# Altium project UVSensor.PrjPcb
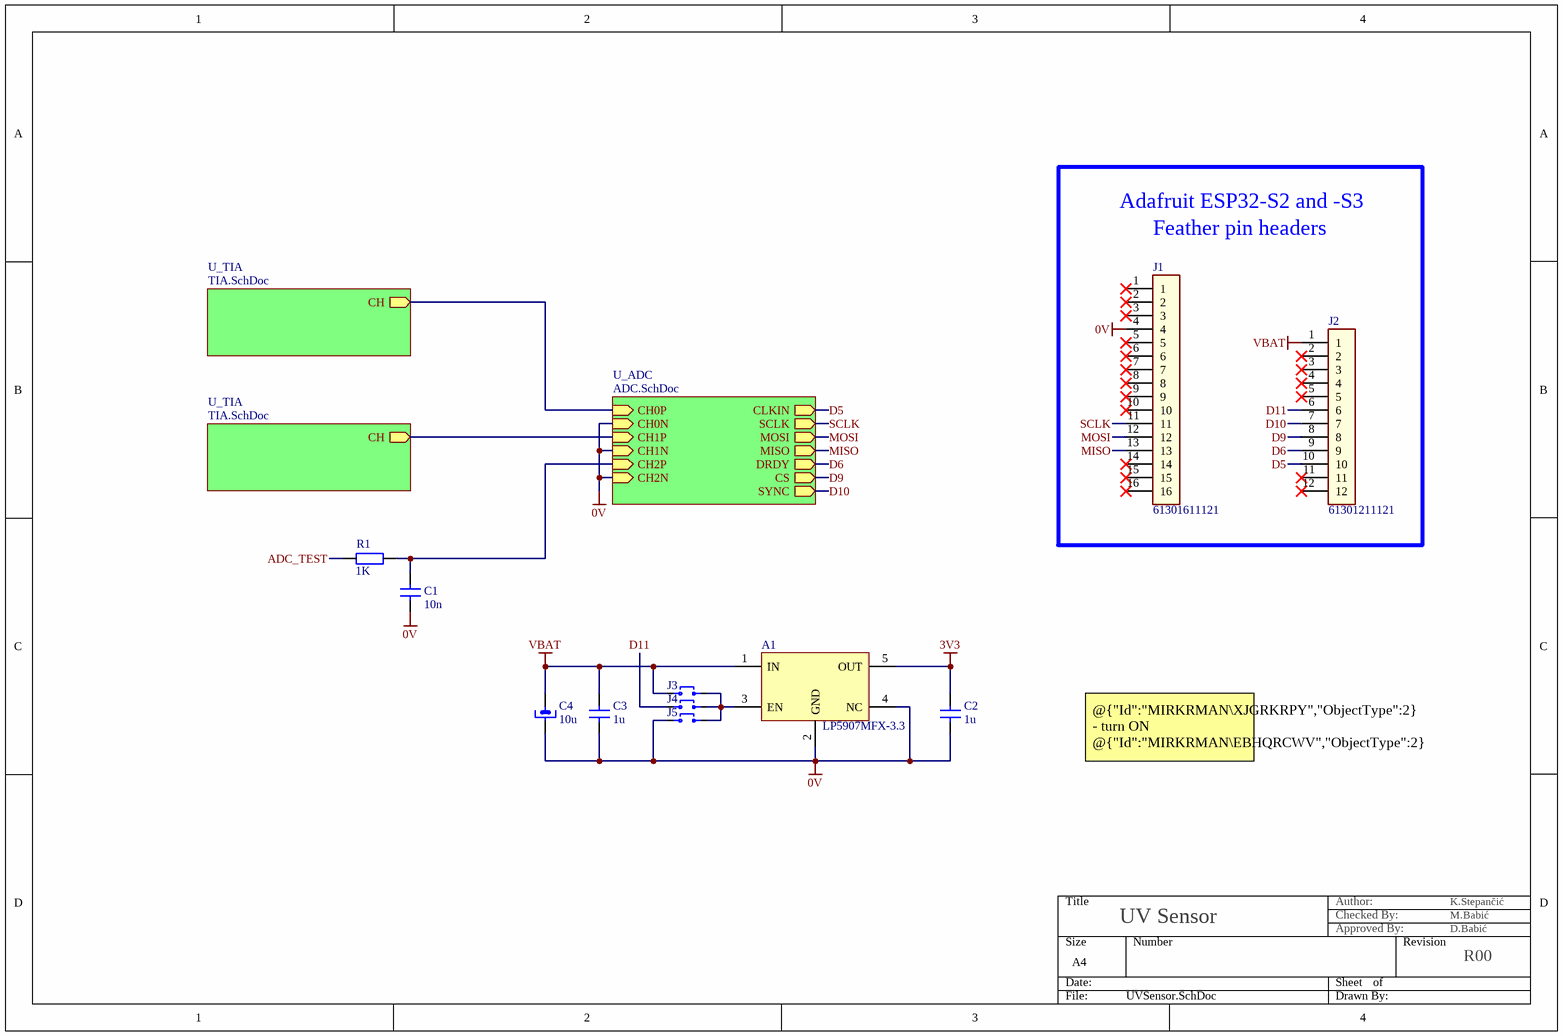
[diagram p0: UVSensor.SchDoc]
K_ApprovedBy: D.Babić; K_AssyNum: A00Z0NE; K_AssyRevision: 00; K_AssySheet: 1; K_AssySheetL1: 1; K_AssySheetL2: 2; K_AssySheetL3: 3; K_AssySheetL4: 4; K_AssySheets: 4; K_Fiet: fiet 40422a/2; K_FIET: fiet 40422a/2; K_LMOSheet: 1; K_LMOSheets: 1; K_PcbDate: 29.5.2025.; K_PcbNum: PB00TIA; K_PcbRevision: 00; K_SchAuthor: K.Stepančić; K_SchCheckedBy: M.Babić; K_SchDate: 29.5.2025.; K_SchNum: S00Z0NE; K_SchRevision: 00; K_Title: UV SENSOR; K_Title1: FerSat; VariantDescription: --
3 sheets, 63 parts. Net scope: hierarchical (ports join the sheet entries above them; power ports are global).
Board file: PB00TIA.PcbDoc
Sheets:
  UVSensor.SchDoc
    U_ADC = ADC.SchDoc
    U_TIA = TIA.SchDoc
    U_TIA = TIA.SchDoc

## Sheet UVSensor.SchDoc: UV Sensor
size A4; ApprovedBy: D.Babić; CheckedBy: M.Babić; Author: K.Stepančić; DrawnBy: K.Stepančić; Engineer: K.Stepančić; DocumentNumber: S00Z0NE; Revision: R00; SheetNumber: 1; SheetTotal: 3; SheetName1: Sensor Board UV; PageSetup: Record=PageOptions¦CenterHorizontal=True¦CenterVertical=True¦PrintScale=1.01¦XCorrection=1.00¦YCorrection=1.00¦PrintKind=0¦BorderSize=5000000¦LeftOffset=0¦BottomOffset=0¦Orientation=2¦PaperLength=1000¦PaperWidth=1000¦Scale=100¦PaperSource=7¦PrintQuality=600¦MediaType=1¦DitherType=10¦PaperKind=A3¦PrintScaleMode=1; SheetName2: SheetName2

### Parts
A1  value LP5907MFX-3.3  [SOT95P280X145-5M]  (hidden comment: LP5907MFX-3.3/NOPB)
C1  10n  [CAPC2012X14M]
C2  1u  [CAPC2012X14M]
C3  1u  [CAPC2012X14M]
C4  value 10u  [CAPMP7343X31M]  (hidden comment: TC_LESR_10u_35V_20%)
J1  61301611121  [HDRV16W79P0X254_1X16_4064X254X874P]
J2  61301211121  [HDRV12W79P0X254_1X12_3048X254X874P]
J3  61300211121  [HDRV2W110P0X254_1X2_508X254X854P]  (value not drawn)
J4  61300211121  [HDRV2W110P0X254_1X2_508X254X854P]  (value not drawn)
J5  61300211121  [HDRV2W110P0X254_1X2_508X254X854P]  (value not drawn)
R1  1K  [RESC2112X05M]

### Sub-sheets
U_ADC = ADC.SchDoc: CH0P (in), CH0N (in), CH1N (in), CH1P (in), CH2P (in), CH2N (in), MOSI (out), MISO (out), SCLK (out), DRDY (out), CS (out), SYNC (out), CLKIN (out)
U_TIA = TIA.SchDoc: CH (out)
U_TIA = TIA.SchDoc: CH (out)

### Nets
0V: A1.2(GND) A1.4(NC) C1.2 C2.2 C3.2 C4.2 J1.4 J5.2 ; sheet U_ADC/CH0N, sheet U_ADC/CH1N, sheet U_ADC/CH2N
3V3: A1.5(OUT) C2.1
VBAT: A1.1(IN) C3.1 C4.1 J2.1 J3.2
ADC_TEST: R1.1
D5: J2.10 ; sheet U_ADC/CLKIN
D6: J2.9 ; sheet U_ADC/DRDY
D9: J2.8 ; sheet U_ADC/CS
D10: J2.7 ; sheet U_ADC/SYNC
D11: J2.6 J4.2
MISO: J1.13 ; sheet U_ADC/MISO
MOSI: J1.12 ; sheet U_ADC/MOSI
SCLK: J1.11 ; sheet U_ADC/SCLK
NetA1_3: A1.3(EN) J3.1 J4.1 J5.1
NetC1_1: C1.1 R1.2 ; sheet U_ADC/CH2P
NetC12:1_1: sheet U_ADC/CH0P, sheet U_TIA/CH
NetC12:2_1: sheet U_ADC/CH1P, sheet U_TIA/CH

Not connected (* = marked no-connect by the designer): J1 1* 2* 3* 5* 6* 7* 8* 9* 10* 14* 15* 16*; J2 2* 3* 4* 5* 11* 12*

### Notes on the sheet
- Adafruit ESP32-S2 and -S3
- (near J1) Feather pin headers
- @{"Id":"MIRKRMAN\XJGRKRPY","ObjectType":2} - turn ON
  @{"Id":"MIRKRMAN\EBHQRCWV","ObjectType":2} - control with GPIO11
  @{"Id":"MIRKRMAN\NMVCMQXM","ObjectType":2} - turn OFF
- Author:
- Checked By:
- Approved By:

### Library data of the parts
A1 = CMP-1291-0A: LDO Voltage Regulators 250mA Ultra-Lo Noise LDO Reg; Manufacturer: Texas Instruments; Voltage: 2.2V to 5.5V
C1 = CAPC2012X14M: C0805H103K5GACTU, / Multilayer Ceramic Capacitors MLCC - SMD/SMT 50V 0.01uF C0G 0805 10%
C2 C3 = CAPC2012X14M: C0805C105K5RACTU, Multilayer Ceramic Capacitors MLCC - SMD/SMT 50V 1uF X7R 0805 10%
C4 = CMP-0312-0D: Capacitor, Tantalum, 10uF, 35V, 20%, Low ESR, 250mΩ, Kemet; ManufacturerPartNumber: T495D106M035ATE250; ValueNumeric: 10000000
J1 = 61301611121: Connector; Manufacturer_Name: Wurth Elektronik
J2 = 61301211121: Connector; Manufacturer_Name: Wurth Elektronik
J3-J5 = 61300211121: Connector; Manufacturer_Name: Wurth Elektronik
R1 = RESC2112X05M: CRCW08051K00JNEC, Thick Film Resistors D12/CRCW0805 200 1K0 5% ET6 e3

## Sheet ADC.SchDoc: ADC
size A4; ApprovedBy: D.Babić; CheckedBy: M.Babić; Author: K.Stepančić; Revision: R00; SheetNumber: 3; SheetTotal: 3
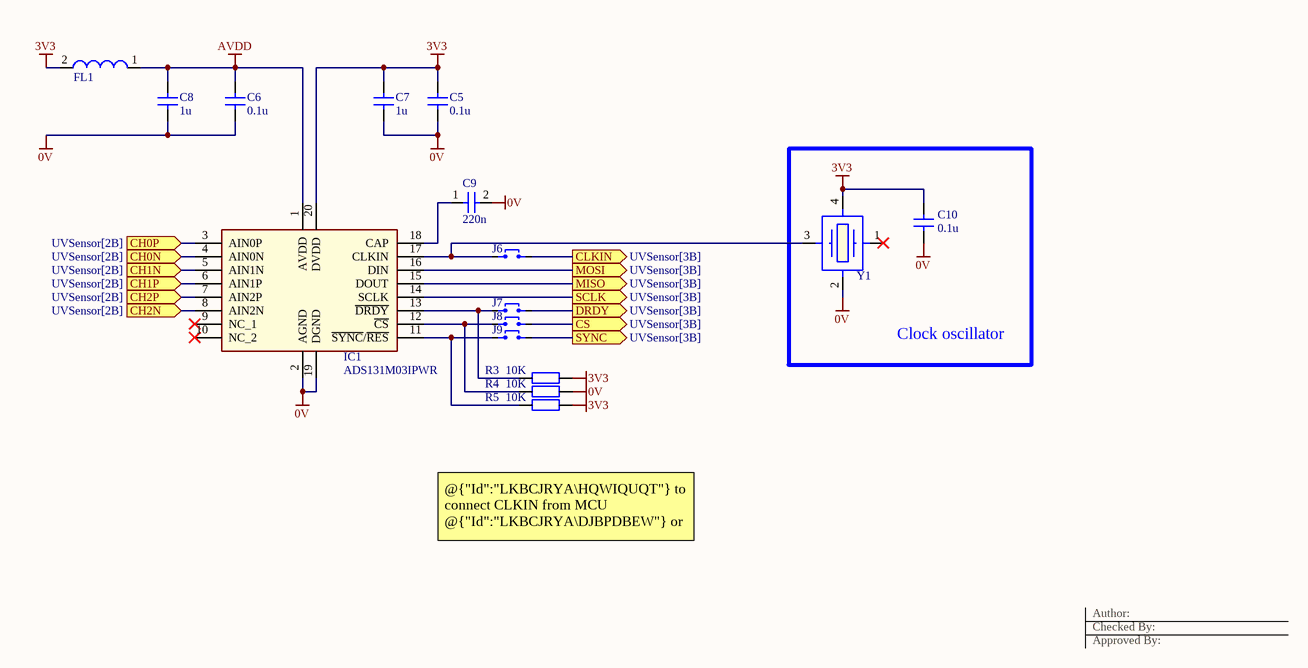
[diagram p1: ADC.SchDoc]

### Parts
C5  0.1u  [CAPC2012X14M]
C6  0.1u  [CAPC2012X14M]
C7  1u  [CAPC2012X14M]
C8  1u  [CAPC2012X14M]
C9  220n  [C_0603]
C10  0.1u  [CAPC2012X14M]
FL1  BLM21SP601BH1D  [BLM21AG102BH1J]  (value not drawn)
IC1  ADS131M03IPWR  [SOP65P640X120-20N]
J6  61300211121  [HDRV2W110P0X254_1X2_508X254X854P]  (value not drawn)
J7  61300211121  [HDRV2W110P0X254_1X2_508X254X854P]  (value not drawn)
J8  61300211121  [HDRV2W110P0X254_1X2_508X254X854P]  (value not drawn)
J9  61300211121  [HDRV2W110P0X254_1X2_508X254X854P]  (value not drawn)
R3  10K  [RESC2112X05M]
R4  10K  [RESC2112X05M]
R5  10K  [RESC2112X05M]
Y1  ECS-2520MVLC-020-BN-TR  [ECS2520MVLC020BNTR]  (value not drawn)

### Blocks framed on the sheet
Clock oscillator: C10 Y1

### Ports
CH0N (in, see UVSensor[2B]), CH0P (in, see UVSensor[2B]), CH1N (in, see UVSensor[2B]), CH1P (in, see UVSensor[2B]), CH2N (in, see UVSensor[2B]), CH2P (in, see UVSensor[2B]), CLKIN (out, see UVSensor[3B]), CS (out, see UVSensor[3B]), DRDY (out, see UVSensor[3B]), MISO (out, see UVSensor[3B]), MOSI (out, see UVSensor[3B]), SCLK (out, see UVSensor[3B]), SYNC (out, see UVSensor[3B])

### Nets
0V: C5.2 C6.2 C7.2 C8.2 C9.2 C10.2 IC1.2(AGND) IC1.4(AIN0N) IC1.5(AIN1N) IC1.8(AIN2N) IC1.19(DGND) R4.2 Y1.2(GND) ; port CH0N, port CH1N, port CH2N
3V3: C5.1 C7.1 C10.1 FL1.2 IC1.20(DVDD) R3.2 R5.2 Y1.4(VDD)
AVDD: C6.1 C8.1 FL1.1 IC1.1(AVDD)
D5: J6.2 ; port CLKIN
D6: J7.2 ; port DRDY
D9: J8.2 ; port CS
D10: J9.2 ; port SYNC
MISO: IC1.15(DOUT) ; port MISO
MOSI: IC1.16(DIN) ; port MOSI
SCLK: IC1.14(SCLK) ; port SCLK
NetC1_1: IC1.7(AIN2P) ; port CH2P
NetC9_1: C9.1 IC1.18(CAP)
NetC12:1_1: IC1.3(AIN0P) ; port CH0P
NetC12:2_1: IC1.6(AIN1P) ; port CH1P
NetIC1_11: IC1.11(~{SYNC}/~{RES}) J9.1 R5.1
NetIC1_12: IC1.12(~{CS}) J8.1 R4.1
NetIC1_13: IC1.13(~{DRDY}) J7.1 R3.1
NetIC1_17: IC1.17(CLKIN) J6.1 Y1.3(OUTPUT)

Not connected (* = marked no-connect by the designer): IC1 9(NC_1)* 10(NC_2)*; Y1 1(TRI-STATE)*

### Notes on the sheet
- @{"Id":"LKBCJRYA\HQWIQUQT"} to connect CLKIN from MCU
  @{"Id":"LKBCJRYA\DJBPDBEW"} or @{"Id":"LKBCJRYA\RAQNGLEC"} to select DRDY or SYNC
  @{"Id":"LKBCJRYA\YJMZBBWQ"} to enable CS
- Author:
- Checked By:
- Approved By:

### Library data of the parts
C5 C6 C10 = CAPC2012X14M: C0805C104K5RACTU, Multilayer Ceramic Capacitors MLCC - SMD/SMT 50V 0.1uF X7R 0805 10%
C7 C8 = CAPC2012X14M: as C2 on sheet UVSensor
C9 = CAP_0603: Capacitor 0603
FL1 = BLM21SP601BH1D: BLM18PG181SN1D; Manufacturer_Name: Murata Electronics
IC1 = ADS131M03IPWR: Integrated Circuit; Manufacturer_Name: Texas Instruments
J6-J9 = 61300211121: as J3 on sheet UVSensor
R3-R5 = RESC2112X05M: CRCW080510K0FKEA, Thick Film Resistors 1/8watt 10Kohms 1% 100ppm
Y1 = ECS-2520MVLC-020-BN-TR: ECS-2520MVLC-081.92-BN-TR, Standard Clock Oscillators MultiVolt ECS-2520MVLC,Active,XO (Standard),8.192MHz,Enable/Disable,CMOS,1.8V, 2.5V, 3.3V,+/-50ppm,-40 C 85 C,Surface Mount,4-SMD, No Lead,0.098" L x 0.079" W (2.50mm x 2.00mm),0.035" (0.90mm); Manufacturer_Name: ECS

## Sheet TIA.SchDoc: TIA LMP7721
size A4; ApprovedBy: D.Babić; CheckedBy: M.Babić; Author: K.Stepančić; Revision: R00; SheetNumber: 2; SheetTotal: 3
Used 2 times, as channels U_TIA, U_TIA. Parts and nets are listed once, with the designators drawn on the sheet.
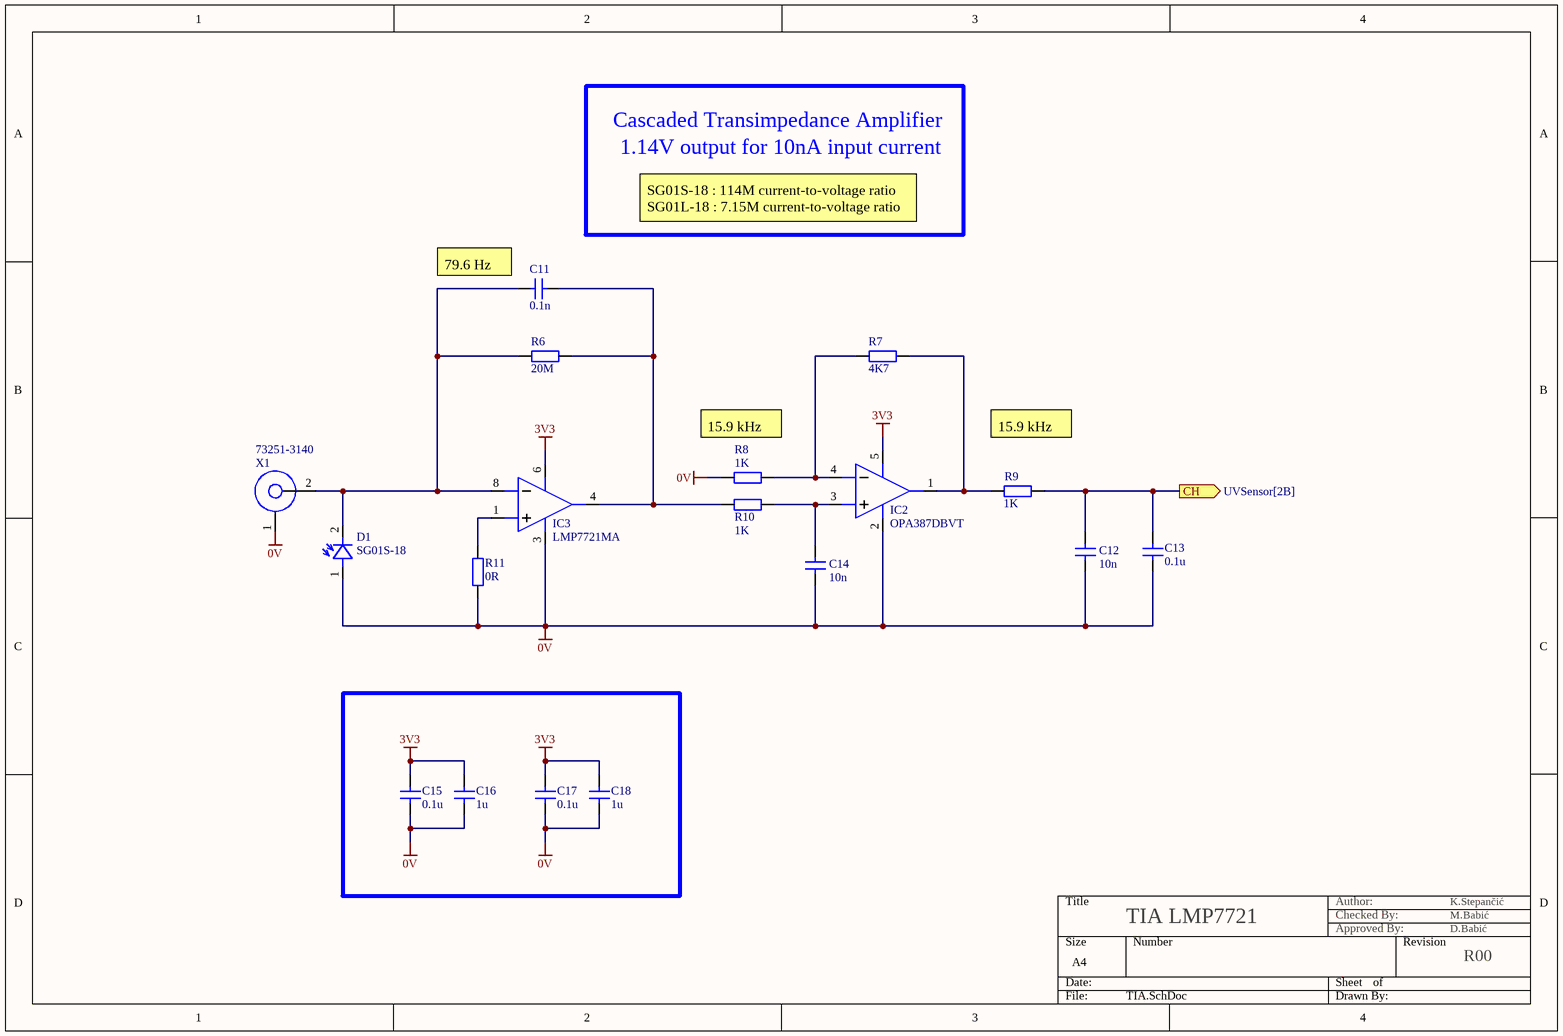
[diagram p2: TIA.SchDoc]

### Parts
C11  0.1n  [CAPC2012X14M]
C12  10n  [CAPC2012X14M]
C13  0.1u  [CAPC2012X14M]
C14  10n  [CAPC2012X14M]
C15  0.1u  [CAPC2012X14M]
C16  1u  [CAPC2012X14M]
C17  0.1u  [CAPC2012X14M]
C18  1u  [CAPC2012X14M]
D1  SG01S-18  [TO18]
IC2  OPA387DBVT  [SOT95P280X145-5N]
IC3  LMP7721MA  [SOIC127P600X175-8N]
R6  20M  [RESC3216X76N]
R7  value 4K7  [RESC2112X05M]  (hidden comment: RES_4K7_0805_1%)
R8  1K  [RESC2112X05M]
R9  1K  [RESC2112X05M]
R10  1K  [RESC2112X05M]
R11  0R  [RESC2112X05M]
X1  73251-3140  [73251-3140]

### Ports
CH (out, see UVSensor[2B])

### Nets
0V: C12.2 C13.2 C14.2 C15.2 C16.2 C17.2 C18.2 D1.1(A) IC2.2(V-) IC3.3(V-) R8.1 R11.1 X1.1
3V3: C15.1 C16.1 C17.1 C18.1 IC2.5(V+) IC3.6(V+)
CH: C12.1 C13.1 R9.2 ; port CH
NetC11_1: C11.1 D1.2(C) IC3.8(IN-) R6.1 X1.2
NetC11_2: C11.2 IC3.4(VOUT) R6.2 R10.1
NetC14_1: C14.1 IC2.3(+IN) R10.2
NetIC2_1: IC2.1(OUT) R7.2 R9.1
NetIC2_4: IC2.4(-IN) R7.1 R8.2
NetIC3_1: IC3.1(IN+) R11.2

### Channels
U_TIA: designators end in :2; ports CH=NetC12:2_1
U_TIA: designators end in :1; ports CH=NetC12:1_1

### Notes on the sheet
- Cascaded Transimpedance Amplifier
- 1.14V output for 10nA input current
- SG01S-18 : 114M current-to-voltage ratio
  SG01L-18 : 7.15M current-to-voltage ratio
- (near C11) 79.6 Hz
- (near R8) 15.9 kHz
- 15.9 kHz
- Author:
- Checked By:
- Approved By:

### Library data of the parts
C11 = CAPC2012X14M: C0805C101J5GAC3123, / Multilayer Ceramic Capacitors MLCC - SMD/SMT 50V 100pF C0G 0805 5%
C12 C14 = CAPC2012X14M: as C1 on sheet UVSensor
C13 C15 C17 = CAPC2012X14M: as C5 on sheet ADC
C16 C18 = CAPC2012X14M: as C2 on sheet UVSensor
D1 = SG01-TO18: SG01 series photodiode, TO18 housing
IC2 = OPA387DBVT: Integrated Circuit; Manufacturer_Name: Texas Instruments
IC3 = LMP7721MA: Integrated Circuit; Manufacturer_Name: Texas Instruments
R6 = RESC3216X76N: CRHV1206AF20M0FKFT / Thick Film Resistors 20Mohms 1% 100ppm 0.3watt 3-side term
R7 = CMP-0039-0H: Resistor, Thick Film, 4K7, 1%, 0.125W, TK100, Vishay; ManufacturerPartNumber: CRCW08054K70FKEA; ValueNumeric: 4700
R8-R10 = RESC2112X05M: as R1 on sheet UVSensor
R11 = RESC2112X05M
X1 = CMP-1058-0A: Connector, Receptacle, SMA, RF, 50Ohm, Molex

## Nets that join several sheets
0V: UVSensor (8 pins), ADC (13 pins), U_TIA (13 pins), U_TIA (13 pins)
3V3: UVSensor (A1.5 C2.1), ADC (8 pins), U_TIA (6 pins), U_TIA (6 pins)
D5: UVSensor (J2.10), ADC (J6.2)
D6: UVSensor (J2.9), ADC (J7.2)
D9: UVSensor (J2.8), ADC (J8.2)
D10: UVSensor (J2.7), ADC (J9.2)
MISO: UVSensor (J1.13), ADC (IC1.15)
MOSI: UVSensor (J1.12), ADC (IC1.16)
NetC1_1: UVSensor (C1.1 R1.2), ADC (IC1.7)
NetC12:1_1: ADC (IC1.3), U_TIA (C12:1.1 C13:1.1 R9:1.2)
NetC12:2_1: ADC (IC1.6), U_TIA (C12:2.1 C13:2.1 R9:2.2)
SCLK: UVSensor (J1.11), ADC (IC1.14)

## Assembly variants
Variant of UVSensor: not fitted C13:1 C13:2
